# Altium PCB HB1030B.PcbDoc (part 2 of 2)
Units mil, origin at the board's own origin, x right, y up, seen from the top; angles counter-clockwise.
Board outline 1259.84 x 2086.61 mil, 2 copper layers (Top Layer, Bottom Layer); 36 components, 40 nets, 161 pads, 288 vias.
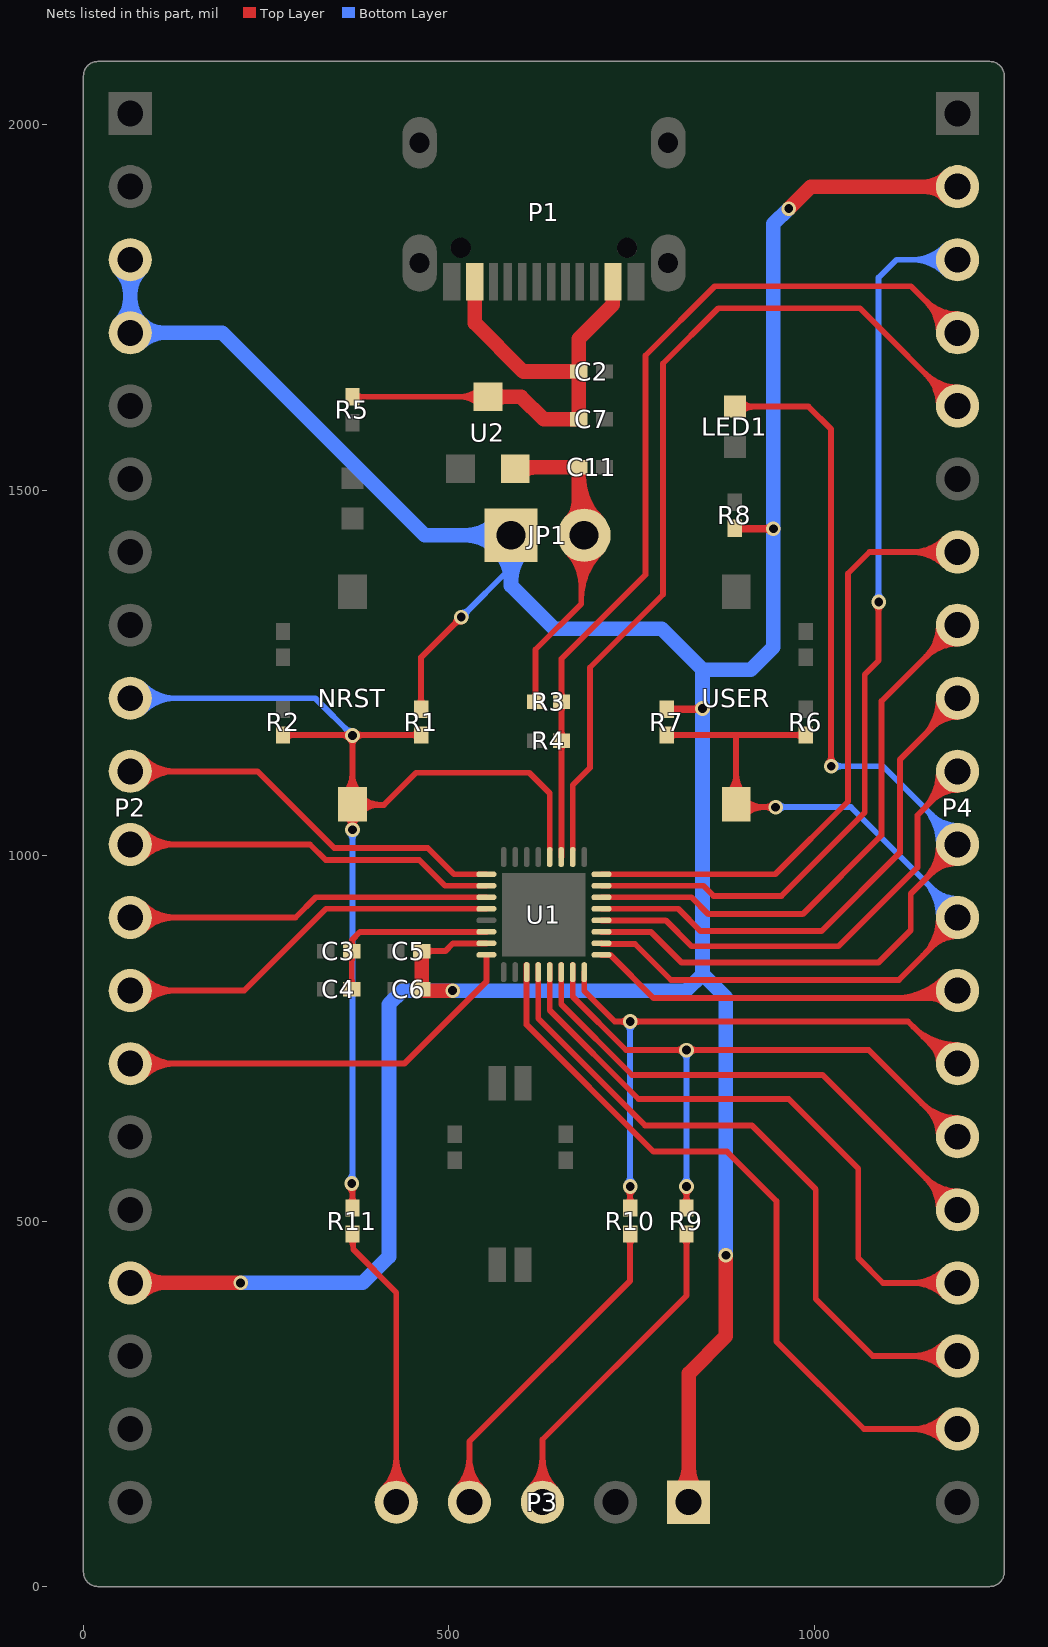
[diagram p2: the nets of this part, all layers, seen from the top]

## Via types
v1: diameter 20, hole 12, Top Layer to Bottom Layer, tented both sides, 284 vias
v2: diameter 25.98, hole 12.99, Top Layer to Bottom Layer, tented top, 4 vias

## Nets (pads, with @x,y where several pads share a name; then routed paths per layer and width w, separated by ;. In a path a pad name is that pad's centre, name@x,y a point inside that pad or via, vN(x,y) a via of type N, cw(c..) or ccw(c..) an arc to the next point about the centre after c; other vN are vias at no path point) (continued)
PA4: P2.10 U1.9 | length 713.9
  Top Layer w8: P2.10@59,1115.37 P2.10@64,1115.37 238,1115.37 343,1010.37 471,1010.37 506.88,974.49 U1.9@551.26,974.49 ; P2.10@76.39,1102.98 cw(c106.32,1073.06) 106.32,1115.37 cw(c106.32,1157.69) P2.10@76.39,1127.77 ; P2.10@82.05,1097.32 cw(c125.63,1053.75) 125.63,1115.37 cw(c125.63,1177) P2.10@82.05,1133.42
PA5: P2.11 U1.10 | length 679
  Top Layer w8: P2.11@59,1015.37 P2.11@64,1015.37 310,1015.37 331.4,993.97 459.4,993.97 494.63,958.74 U1.10@551.26,958.74 ; P2.11@76.39,1002.98 cw(c106.32,973.06) 106.32,1015.37 cw(c106.32,1057.69) P2.11@76.39,1027.77 ; P2.11@82.05,997.32 cw(c125.63,953.75) 125.63,1015.37 cw(c125.63,1077) P2.11@82.05,1033.42
PA6: P2.12 U1.11 | length 662.9
  Top Layer w8: P2.12@64,915.37 290,915.37 317.62,943 U1.11@551.26,943 ; P2.12@68.62,905.75 P2.12@69.24,906.37 ; P2.12@76.39,902.98 cw(c106.32,873.06) 106.32,915.37 cw(c106.32,957.69) P2.12@76.39,927.77 ; P2.12@82.05,897.32 cw(c125.63,853.75) 125.63,915.37 cw(c125.63,977) P2.12@82.05,933.42
PA7: P2.13 U1.12 | length 676.9
  Top Layer w8: P2.13@76.39,802.98 cw(c106.32,773.06) 106.32,815.37 cw(c106.32,857.69) P2.13@76.39,827.77 ; P2.13@82.05,797.32 cw(c125.63,753.75) 125.63,815.37 cw(c125.63,877) P2.13@82.05,833.42 ; P2.13@84,815.37 220,815.37 331.87,927.25 U1.12@551.26,927.25
PA8: P2.14 U1.16 | length 738.7
  Top Layer w8: P2.14@59,715.37 439,715.37 551.26,827.63 U1.16@551.26,864.26 ; P2.14@76.39,702.98 cw(c106.32,673.06) 106.32,715.37 cw(c106.32,757.69) P2.14@76.39,727.77 ; P2.14@82.05,697.32 cw(c125.63,653.75) 125.63,715.37 cw(c125.63,777) P2.14@82.05,733.42
PA9: P4.19 U1.19 | length 1181.5
  Top Layer w8: U1.19@606.38,850.63 U1.19@606.38,840.63 606.38,768.62 780,595 880.37,595 948,527.37 948,335.37 1068,215.37 P4.19@1196,215.37 P4.19@1201,215.37 ; P4.19@1177.95,197.32 ccw(c1134.37,153.75) 1134.37,215.37 ccw(c1134.37,277) P4.19@1177.95,233.42 ; P4.19@1183.61,202.98 ccw(c1153.68,173.06) 1153.68,215.37 ccw(c1153.68,257.69) P4.19@1183.61,227.77
PA10: P4.18 U1.20 | length 1094.8
  Top Layer w8: U1.20@622.13,850.63 U1.20@622.13,840.63 622.13,777.03 768.16,631 914.37,631 1002,543.37 1002,393.37 1080,315.37 P4.18@1196,315.37 P4.18@1201,315.37 ; P4.18@1177.95,297.32 ccw(c1134.37,253.75) 1134.37,315.37 ccw(c1134.37,377) P4.18@1177.95,333.42 ; P4.18@1183.61,302.98 ccw(c1153.68,273.06) 1153.68,315.37 ccw(c1153.68,357.69) P4.18@1183.61,327.77
PA11: P4.17 U1.21 | length 1014.9
  Top Layer w8: U1.21@637.87,850.63 U1.21@637.87,840.63 637.87,788.5 759.37,667 965,667 1060,572 1060,449.37 1094,415.37 P4.17@1201,415.37 ; P4.17@1177.95,397.32 ccw(c1134.37,353.75) 1134.37,415.37 ccw(c1134.37,477) P4.17@1177.95,433.42 ; P4.17@1183.61,402.98 ccw(c1153.68,373.06) 1153.68,415.37 ccw(c1153.68,457.69) P4.17@1183.61,427.77
PA12: P4.16 U1.22 | length 886.8
  Top Layer w8: U1.22@653.62,829.95 U1.22@653.62,840.63 ; U1.22@653.62,850.63 U1.22@653.62,840.63 ; P4.16@1170.47,515.37 ccw(c1108.84,515.37) 1152.42,558.95 ccw(c1196,602.53) P4.16@1196,540.9 ; P4.16@1178.47,515.37 ccw(c1136.16,515.37) 1166.08,545.3 ccw(c1196,575.22) P4.16@1196,532.9 ; P4.16@1196,515.37 1011.37,700 750.37,700 653.62,796.75 U1.22@653.62,840.63
PA13: P4.15 R9.1 U1.23 | length 1311.2
  Top Layer w8: U1.23@669.37,835.42 U1.23@669.37,840.63 ; U1.23@669.37,850.63 U1.23@669.37,840.63 ; R9.1@825,517.81 v1(825,547.37) ; 1147.3,661.07 ccw(c1196,709.77) P4.15@1196,640.9 ; 1154.54,653.83 cw(c1116.09,615.37) P4.15@1170.47,615.37 ; 1160.96,647.42 ccw(c1196,682.46) P4.15@1196,632.9 ; 1168.2,640.17 cw(c1143.4,615.37) P4.15@1178.47,615.37 ; P4.15@1201,615.37 1193,615.37 1074.37,734 742.37,734 669.37,807 U1.23@669.37,840.63 ; 810.51,734 cw(c810.51,719.51) 820.76,729.76 ccw(c810.51,719.51) 810.51,734 ; 810.51,734 ccw(c810.51,748.49) 820.76,738.24 cw(c810.51,748.49) 810.51,734 ; 825,532.89 cw(c839.49,532.89) 829.24,543.13 ccw(c839.49,532.89) 825,532.89 ; 825,532.89 ccw(c810.51,532.89) 820.76,543.13 cw(c810.51,532.89) 825,532.89 ; 825,533.88 cw(c810.9,533.88) 820.87,523.91 ccw(c810.9,533.88) 825,533.88 ; 825,533.88 ccw(c839.1,533.88) 829.13,523.91 cw(c839.1,533.88) 825,533.88 ; 839.49,734 cw(c839.49,748.49) 829.24,738.24 ccw(c839.49,748.49) 839.49,734 ; 839.49,734 ccw(c839.49,719.51) 829.24,729.76 cw(c839.49,719.51) 839.49,734
  Bottom Layer w8: v1(825,547.37) v1(825,734) ; 825,561.86 cw(c810.51,561.86) 820.76,551.62 ccw(c810.51,561.86) 825,561.86 ; 825,561.86 ccw(c839.49,561.86) 829.24,551.62 cw(c839.49,561.86) 825,561.86 ; 825,719.51 cw(c839.49,719.51) 829.24,729.76 ccw(c839.49,719.51) 825,719.51 ; 825,719.51 ccw(c810.51,719.51) 820.76,729.76 cw(c810.51,719.51) 825,719.51
PA14: P4.14 R10.1 U1.24 | length 1298.8
  Top Layer w8: U1.24@685.12,840.63 685.12,814.88 727,773 1128,773 1185.63,715.37 P4.14@1201,715.37 ; R10.1@748,517.81 v1(748,547.37) ; 1134.71,766.29 ccw(c1196,827.58) P4.14@1196,740.9 ; 1148.37,752.63 ccw(c1196,800.26) P4.14@1196,732.9 ; 1159.76,741.24 cw(c1133.89,715.37) P4.14@1170.47,715.37 ; 1162.03,738.97 ccw(c1196,772.95) P4.14@1196,724.9 ; P4.14@1195,716.37 P4.14@1196,715.37 ; 733.51,773 cw(c733.51,758.51) 743.76,768.76 ccw(c733.51,758.51) 733.51,773 ; 733.51,773 ccw(c733.51,787.49) 743.76,777.24 cw(c733.51,787.49) 733.51,773 ; 748,532.89 cw(c762.49,532.89) 752.24,543.13 ccw(c762.49,532.89) 748,532.89 ; 748,532.89 ccw(c733.51,532.89) 743.76,543.13 cw(c733.51,532.89) 748,532.89 ; 748,533.88 cw(c733.9,533.88) 743.87,523.91 ccw(c733.9,533.88) 748,533.88 ; 748,533.88 ccw(c762.1,533.88) 752.13,523.91 cw(c762.1,533.88) 748,533.88 ; 762.49,773 cw(c762.49,787.49) 752.24,777.24 ccw(c762.49,787.49) 762.49,773 ; 762.49,773 ccw(c762.49,758.51) 752.24,768.76 cw(c762.49,758.51) 762.49,773
  Bottom Layer w8: v1(748,547.37) v1(748,773) ; 748,561.86 cw(c733.51,561.86) 743.76,551.62 ccw(c733.51,561.86) 748,561.86 ; 748,561.86 ccw(c762.49,561.86) 752.24,551.62 cw(c762.49,561.86) 748,561.86 ; 748,758.51 cw(c762.49,758.51) 752.24,768.76 ccw(c762.49,758.51) 748,758.51 ; 748,758.51 ccw(c733.51,758.51) 743.76,768.76 cw(c733.51,758.51) 748,758.51
PA15: P4.13 U1.25 | length 754.1
  Top Layer w8: U1.25@708.74,864.26 720.74,864.26 780,805 1185.63,805 P4.13@1196,815.37 ; 1109.33,805 ccw(c1109.33,902.05) P4.13@1177.95,833.42 ; 1128.64,805 ccw(c1128.64,882.73) P4.13@1183.61,827.77 ; 1147.95,805 ccw(c1147.95,863.42) P4.13@1189.26,822.11 ; 1159.42,805 cw(c1159.42,778.79) P4.13@1177.95,797.32 ; 1167.27,805 ccw(c1167.27,844.11) P4.13@1194.92,816.45 ; P4.13@1198.5,812.87 P4.13@1201,815.37
PB3: P4.12 R6.2 R7.1 U1.26 USER.2 | length 1885.5
  Top Layer w8: U1.26@708.74,880 709.49,879.26 754.74,879.26 804,830 1115.63,830 P4.12@1201,915.37 ; R7.1@798,1164.94 893,1164.94 ; USER.2@881.91,1085.06 ccw(c855.13,1111.84) 893,1111.84 ccw(c930.87,1111.84) USER.2@904.09,1085.06 ; USER.2@904.09,1055.01 cw(c931.53,1027.57) 931.53,1066.37 ; USER.2@904.09,1077.19 ccw(c930.2,1103.3) 930.2,1066.37 ; v1(947,1066.37) 896.66,1066.37 USER.2@893,1070.04 893,1164.94 ; R6.2@988,1164.94 893,1164.94 ; 1148.89,863.26 ccw(c1096.77,915.37) P4.12@1170.47,915.37 ; 1160.96,875.33 cw(c1196,840.29) P4.12@1196,889.85 ; 1162.54,876.92 ccw(c1124.09,915.37) P4.12@1178.47,915.37 ; 1174.61,888.99 cw(c1196,867.6) P4.12@1196,897.85 ; 1176.2,890.57 ccw(c1151.4,915.37) P4.12@1186.47,915.37 ; 812.1,1164.94 cw(c812.1,1179.05) 802.13,1169.07 ccw(c812.1,1179.05) 812.1,1164.94 ; 812.1,1164.94 ccw(c812.1,1150.84) 802.13,1160.81 cw(c812.1,1150.84) 812.1,1164.94 ; 932.51,1066.37 cw(c932.51,1051.89) 942.76,1062.13 ccw(c932.51,1051.89) 932.51,1066.37 ; 932.51,1066.37 ccw(c932.51,1080.86) 942.76,1070.62 cw(c932.51,1080.86) 932.51,1066.37 ; 973.9,1164.94 cw(c973.9,1150.84) 983.87,1160.81 ccw(c973.9,1150.84) 973.9,1164.94 ; 973.9,1164.94 ccw(c973.9,1179.05) 983.87,1169.07 cw(c973.9,1179.05) 973.9,1164.94
  Bottom Layer w8: v1(947,1066.37) 1050,1066.37 P4.12@1201,915.37 ; 1148.89,967.49 cw(c1096.77,915.37) P4.12@1170.47,915.37 ; 1160.96,955.42 ccw(c1196,990.46) P4.12@1196,940.9 ; 1162.54,953.83 cw(c1124.09,915.37) P4.12@1178.47,915.37 ; 1174.61,941.76 ccw(c1196,963.15) P4.12@1196,932.9 ; 1176.2,940.17 cw(c1151.4,915.37) P4.12@1186.47,915.37 ; 961.49,1066.37 cw(c961.49,1080.86) 951.24,1070.62 ccw(c961.49,1080.86) 961.49,1066.37 ; 961.49,1066.37 ccw(c961.49,1051.89) 951.24,1062.13 cw(c961.49,1051.89) 961.49,1066.37
PB4: LED1.2 P4.11 U1.27 | length 1959
  Top Layer w8: U1.27@708.74,895.75 776.25,895.75 818,854 1088,854 1132,898 1132,948 1196,1012 P4.11@1196,1015.37 ; LED1.2@891.35,1614.37 992,1614.37 1023,1583.37 v1(1023,1122.37) ; 1150.04,966.04 ccw(c1100.7,1015.37) P4.11@1170.47,1015.37 ; 1158.18,974.18 cw(c1196,936.36) P4.11@1196,989.85 ; 1163.69,979.69 ccw(c1128.01,1015.37) P4.11@1178.47,1015.37 ; 1171.84,987.84 cw(c1196,963.68) P4.11@1196,997.85 ; 917.9,1614.37 cw(c917.9,1640.93) 899.12,1622.15 ccw(c917.9,1640.93) 917.9,1614.37 ; 917.9,1614.37 ccw(c917.9,1587.82) 899.12,1606.6 cw(c917.9,1587.82) 917.9,1614.37 ; 1023,1136.86 cw(c1008.51,1136.86) 1018.76,1126.62 ccw(c1008.51,1136.86) 1023,1136.86 ; 1023,1136.86 ccw(c1037.49,1136.86) 1027.24,1126.62 cw(c1037.49,1136.86) 1023,1136.86
  Bottom Layer w8: v1(1023,1122.37) 1094,1122.37 P4.11@1201,1015.37 ; 1148.89,1067.49 cw(c1096.77,1015.37) P4.11@1170.47,1015.37 ; 1160.96,1055.42 ccw(c1196,1090.46) P4.11@1196,1040.9 ; 1162.54,1053.83 cw(c1124.09,1015.37) P4.11@1178.47,1015.37 ; 1174.61,1041.76 ccw(c1196,1063.15) P4.11@1196,1032.9 ; 1176.2,1040.17 cw(c1151.4,1015.37) P4.11@1186.47,1015.37 ; 1037.49,1122.37 cw(c1037.49,1136.86) 1027.24,1126.62 ccw(c1037.49,1136.86) 1037.49,1122.37 ; 1037.49,1122.37 ccw(c1037.49,1107.89) 1027.24,1118.13 cw(c1037.49,1107.89) 1037.49,1122.37
PB5: P4.10 U1.28 | length 838.7
  Top Layer w8: U1.28@708.74,911.5 796.5,911.5 832,876 1033,876 1141,984 1141,1055.37 P4.10@1201,1115.37 ; 1148.89,1063.26 ccw(c1096.77,1115.37) P4.10@1170.47,1115.37 ; 1160.96,1075.33 cw(c1196,1040.29) P4.10@1196,1089.85 ; 1162.54,1076.92 ccw(c1124.09,1115.37) P4.10@1178.47,1115.37 ; 1174.61,1088.99 cw(c1196,1067.6) P4.10@1196,1097.85 ; 1176.2,1090.57 ccw(c1151.4,1115.37) P4.10@1186.47,1115.37
PB6: P4.9 U1.29 | length 902.1
  Top Layer w8: U1.29@708.74,927.25 813.75,927.25 844,897 1010,897 1117,1004 1117,1131.37 P4.9@1201,1215.37 ; 1148.89,1163.26 ccw(c1096.77,1215.37) P4.9@1170.47,1215.37 ; 1160.96,1175.33 cw(c1196,1140.29) P4.9@1196,1189.85 ; 1162.54,1176.92 ccw(c1124.09,1215.37) P4.9@1178.47,1215.37 ; 1174.61,1188.99 cw(c1196,1167.6) P4.9@1196,1197.85 ; 1176.2,1190.57 ccw(c1151.4,1215.37) P4.9@1186.47,1215.37
PB7: P4.8 U1.30 | length 931.2
  Top Layer w8: U1.30@708.74,943 832,943 855,920 984,920 1092,1028 1092,1211.37 P4.8@1196,1315.37 ; P4.8@1170.47,1315.37 cw(c1108.84,1315.37) 1152.42,1271.8 cw(c1196,1228.22) P4.8@1196,1289.85 ; P4.8@1178.47,1315.37 cw(c1136.16,1315.37) 1166.08,1285.45 cw(c1196,1255.53) P4.8@1196,1297.85
PB8: P4.7 U1.32 | length 1015.9
  Top Layer w8: U1.32@708.74,974.49 946.49,974.49 1046,1074 1046,1386 1075.37,1415.37 P4.7@1196,1415.37 ; P4.7@1177.95,1397.32 ccw(c1134.37,1353.75) 1134.37,1415.37 ccw(c1134.37,1477) P4.7@1177.95,1433.42 ; P4.7@1183.61,1402.98 ccw(c1153.68,1373.06) 1153.68,1415.37 ccw(c1153.68,1457.69) P4.7@1183.61,1427.77
PF1: P4.5 U1.2 | length 1369.4
  Top Layer w8: U1.2@669.37,1008.11 669.37,1096.74 693,1120.37 693,1257.37 793,1357.37 793,1673.37 868.63,1749 1062.37,1749 P4.5@1196,1615.37 ; P4.5@1170.47,1615.37 ccw(c1108.84,1615.37) 1152.42,1658.95 ccw(c1196,1702.53) P4.5@1196,1640.9 ; P4.5@1178.47,1615.37 ccw(c1136.16,1615.37) 1166.08,1645.3 ccw(c1196,1675.22) P4.5@1196,1632.9
PF2: P4.4 R3.1 R4.1 U1.3 | length 1566.6
  Top Layer w8: U1.3@654,998.49 R4.1@654,1157.37 R3.1@654,1210.37 654,1269.37 769,1384.37 769,1684.37 863.63,1779 1132.37,1779 P4.4@1196,1715.37 ; P4.4@1170.47,1715.37 ccw(c1108.84,1715.37) 1152.42,1758.95 ccw(c1196,1802.53) P4.4@1196,1740.9 ; P4.4@1178.47,1715.37 ccw(c1136.16,1715.37) 1166.08,1745.3 ccw(c1196,1775.22) P4.4@1196,1732.9 ; 654,1143.27 cw(c668.1,1143.27) 658.13,1153.24 ccw(c668.1,1143.27) 654,1143.27 ; 654,1143.27 ccw(c639.9,1143.27) 649.87,1153.24 cw(c639.9,1143.27) 654,1143.27 ; 654,1171.48 cw(c639.9,1171.48) 649.87,1161.51 ccw(c639.9,1171.48) 654,1171.48 ; 654,1171.48 ccw(c668.1,1171.48) 658.13,1161.51 cw(c668.1,1171.48) 654,1171.48 ; 654,1196.27 cw(c668.1,1196.27) 658.13,1206.24 ccw(c668.1,1196.27) 654,1196.27 ; 654,1196.27 ccw(c639.9,1196.27) 649.87,1206.24 cw(c639.9,1196.27) 654,1196.27 ; 654,1224.48 cw(c639.9,1224.48) 649.87,1214.51 ccw(c639.9,1224.48) 654,1224.48 ; 654,1224.48 ccw(c668.1,1224.48) 658.13,1214.51 cw(c668.1,1224.48) 654,1224.48
PF3: NRST.2 P2.9 R1.2 R2.1 R11.1 U1.4 | length 2422.3
  Top Layer w8: R2.1@273,1164.94 v1@367.43,1164.94 ; NRST.2@356.91,1085.06 ccw(c330.13,1111.84) 368,1111.84 ccw(c405.87,1111.84) NRST.2@379.09,1085.06 ; v1(367,551.37) 368,550.37 R11.1@368,517.81 ; v1(368,1164.37) NRST.2@368,1070.04 ; v1@368.57,1164.94 R1.2@462,1164.94 ; NRST.2@373.43,1075.47 ccw(c388.15,1090.19) 388.15,1069.37 ; NRST.2@379.09,1058.94 cw(c404.27,1033.77) 404.27,1069.37 ; NRST.2@379.09,1081.13 ccw(c407.46,1109.5) 407.46,1069.37 ; U1.4@637.87,1008.11 637.87,1085.5 610,1113.37 455,1113.37 411,1069.37 368.66,1069.37 NRST.2@368,1070.04 ; 287.1,1164.94 cw(c287.1,1179.05) 277.13,1169.07 ccw(c287.1,1179.05) 287.1,1164.94 ; 287.1,1164.94 ccw(c287.1,1150.84) 277.13,1160.81 cw(c287.1,1150.84) 287.1,1164.94 ; v1@363.76,1160.13 ccw(c352.15,1148.52) 352.15,1164.94 cw(c352.15,1148.52) v1@363.76,1160.13 ; v1@363.76,1160.13 cw(c353.51,1149.89) 368,1149.89 ; v1@363.76,1160.13 cw(c353.51,1149.89) 368,1149.89 ; 368,533.88 cw(c353.9,533.88) 363.87,523.91 ccw(c353.9,533.88) 368,533.88 ; 368,533.88 ccw(c382.1,533.88) 372.13,523.91 cw(c382.1,533.88) 368,533.88 ; v1(368,1035.37) cw(c390.25,1035.38) 377.2,1053.39 ccw(c390.25,1035.38) v1(368,1035.37) ; v1(368,1035.37) ccw(c345.75,1035.38) 358.8,1053.39 cw(c345.75,1035.38) v1(368,1035.37) ; v1(368,1035.37) NRST.2@368,1070.04 ; NRST.2@368,1049.86 cw(c353.51,1049.86) 363.76,1039.62 ccw(c353.51,1049.86) NRST.2@368,1049.86 ; NRST.2@368,1049.86 ccw(c382.49,1049.86) 372.24,1039.62 cw(c382.49,1049.86) NRST.2@368,1049.86 ; 368,1149.89 cw(c382.49,1149.89) v1@372.24,1160.13 ; 368,1149.89 cw(c382.49,1149.89) v1@372.24,1160.13 ; v1@372.24,1160.13 cw(c383.85,1148.52) 383.85,1164.94 ccw(c383.85,1148.52) v1@372.24,1160.13 ; 447.9,1164.94 cw(c447.9,1150.84) 457.87,1160.81 ccw(c447.9,1150.84) 447.9,1164.94 ; 447.9,1164.94 ccw(c447.9,1179.05) 457.87,1169.07 cw(c447.9,1179.05) 447.9,1164.94 ; 354.88,1164.94 ccw(c354.88,1177.49) 363.76,1168.62 cw(c354.88,1177.49) 354.88,1164.94 ; v1@362.76,547.13 cw(c350.1,534.47) 368,534.47 ccw(c350.1,534.47) v1@362.76,547.13 ; 368,539.3 cw(c379.07,539.3) 371.24,547.13 ccw(c379.07,539.3) 368,539.3 ; v1@372.24,1168.62 ccw(c381.12,1177.49) 381.12,1164.94 cw(c381.12,1177.49) v1@372.24,1168.62
  Bottom Layer w8: P2.9@59,1215.37 P2.9@64,1215.37 317,1215.37 v1(368,1164.37) ; P2.9@76.39,1202.98 cw(c106.32,1173.06) 106.32,1215.37 cw(c106.32,1257.69) P2.9@76.39,1227.77 ; P2.9@82.05,1197.32 cw(c125.63,1153.75) 125.63,1215.37 cw(c125.63,1277) P2.9@82.05,1233.42 ; v1(367,551.37) 368,552.37 v1(368,1035.37) ; 357.76,1174.62 cw(c347.51,1164.37) 362,1164.37 ccw(c347.51,1164.37) 357.76,1174.62 ; 357.76,1174.62 ccw(c368,1184.86) 368,1170.37 cw(c368,1184.86) 357.76,1174.62 ; 368,1020.89 cw(c382.49,1020.89) 372.24,1031.13 ccw(c382.49,1020.89) 368,1020.89 ; 368,1020.89 ccw(c353.51,1020.89) 363.76,1031.13 cw(c353.51,1020.89) 368,1020.89 ; v1@362.76,555.62 ccw(c350.1,568.27) 368,568.27 cw(c350.1,568.27) v1@362.76,555.62 ; 368,563.45 ccw(c379.07,563.45) 371.24,555.62 cw(c379.07,563.45) 368,563.45
PF4: P4.3 U1.31 | length 1525.4
  Top Layer w8: U1.31@708.74,958.74 848.26,958.74 862,945 955,945 1069,1059 1069,1248 1088,1267 v1(1088,1347) ; 1088,1332.51 cw(c1102.49,1332.51) 1092.24,1342.76 ccw(c1102.49,1332.51) 1088,1332.51 ; 1088,1332.51 ccw(c1073.51,1332.51) 1083.76,1342.76 cw(c1073.51,1332.51) 1088,1332.51
  Bottom Layer w8: v1(1088,1347) 1088,1791 1112.37,1815.37 P4.3@1196,1815.37 ; P4.3@1177.95,1797.32 ccw(c1134.37,1753.75) 1134.37,1815.37 ccw(c1134.37,1877) P4.3@1177.95,1833.42 ; P4.3@1183.61,1802.98 ccw(c1153.68,1773.06) 1153.68,1815.37 ccw(c1153.68,1857.69) P4.3@1183.61,1827.77 ; 1088,1361.49 cw(c1073.51,1361.49) 1083.76,1351.24 ccw(c1073.51,1361.49) 1088,1361.49 ; 1088,1361.49 ccw(c1102.49,1361.49) 1092.24,1351.24 cw(c1102.49,1361.49) 1088,1361.49
RESET: P3.5 R11.2 | length 599
  Top Layer w8: R11.2@369,482.37 369,461.37 428,402.37 P3.5@428,115.37 ; P3.5@409.95,133.42 ccw(c366.37,177) 428,177 ccw(c489.63,177) P3.5@446.05,133.42 ; P3.5@415.61,127.77 ccw(c385.68,157.69) 428,157.69 ccw(c470.32,157.69) P3.5@440.39,127.77 ; R11.2@363.87,476.27 cw(c351.48,463.89) 369,463.89 ccw(c351.48,463.89) R11.2@363.87,476.27 ; 369,468.71 cw(c379.69,468.71) 372.13,476.27 ccw(c379.69,468.71) 369,468.71
SWCLK: P3.4 R10.2 | length 677.7
  Top Layer w8: P3.4@509.95,133.42 ccw(c466.37,177) 528,177 ccw(c589.63,177) P3.4@546.05,133.42 ; P3.4@515.61,127.77 ccw(c485.68,157.69) 528,157.69 ccw(c570.32,157.69) P3.4@540.39,127.77 ; P3.4@528,115.37 528,198.37 748,418.37 748,470.37 ; 748,466.3 cw(c762.1,466.3) 752.13,476.27 ccw(c762.1,466.3) 748,466.3 ; 748,466.3 ccw(c733.9,466.3) 743.87,476.27 cw(c733.9,466.3) 748,466.3 ; 748,470.37 cw(c753.69,470.37) 750.88,475.32 ccw(c753.69,470.37) 748,470.37 ; 748,470.37 ccw(c742.31,470.37) 745.12,475.32 cw(c742.31,470.37) 748,470.37
SWDIO: P3.3 R9.2 | length 668.2
  Top Layer w8: P3.3@609.95,133.42 ccw(c566.37,177) 628,177 ccw(c689.63,177) P3.3@646.05,133.42 ; P3.3@615.61,127.77 ccw(c585.68,157.69) 628,157.69 ccw(c670.32,157.69) P3.3@640.39,127.77 ; P3.3@628,115.37 628,201 825,398 825,470.37 ; 825,466.3 cw(c839.1,466.3) 829.13,476.27 ccw(c839.1,466.3) 825,466.3 ; 825,466.3 ccw(c810.9,466.3) 820.87,476.27 cw(c810.9,466.3) 825,466.3 ; 825,470.37 cw(c830.69,470.37) 827.88,475.32 ccw(c830.69,470.37) 825,470.37 ; 825,470.37 ccw(c819.31,470.37) 822.12,475.32 cw(c819.31,470.37) 825,470.37
VBUS_5V: C2.2 C7.2 P1.A4 P1.A9 P1.B4 P1.B9 R5.2 U2.3 | length 933.3
  Top Layer w8: R5.2@368,1627.81 U2.3@553.4,1627.8 ; U2.3@542.31,1616.71 ccw(c515.53,1589.93) 515.53,1627.8 ccw(c515.53,1665.67) U2.3@542.31,1638.89 ; 382.12,1627.8 cw(c382.12,1641.93) 372.13,1631.94 ccw(c382.12,1641.93) 382.12,1627.8 ; 382.09,1627.8 ccw(c382.09,1613.72) 372.13,1623.68 cw(c382.09,1613.72) 382.09,1627.8
  Top Layer w20: P1.B4@535.52,1785.23 535.52,1728.85 602,1662.37 C2.2@677.57,1662.37 ; U2.3@553.4,1627.8 598.57,1627.8 629.5,1596.87 C7.2@677.57,1596.87 C2.2@677.57,1662.37 ; P1.B9@724.31,1785.23 724.31,1753.69 677.57,1706.94 C2.2@677.57,1662.37 ; 576.78,1627.8 cw(c576.78,1651.18) 560.25,1634.65 ccw(c576.78,1651.18) 576.78,1627.8 ; 576.78,1627.8 ccw(c576.78,1604.42) 560.25,1620.95 cw(c576.78,1604.42) 576.78,1627.8
VCORE: C3.1 C4.1 U1.14 | length 389.3
  Top Layer w8: C4.1@367,816.97 367,884.37 378.38,895.75 U1.14@551.26,895.75 ; 367,831.08 cw(c352.9,831.08) 362.87,821.11 ccw(c352.9,831.08) 367,831.08 ; 367,831.08 ccw(c381.1,831.08) 371.13,821.11 cw(c381.1,831.08) 367,831.08 ; 367,855.27 cw(c381.1,855.27) 371.13,865.24 ccw(c381.1,855.27) 367,855.27 ; 367,855.27 ccw(c352.9,855.27) 362.87,865.24 cw(c352.9,855.27) 367,855.27 ; 367,883.48 cw(c352.9,883.48) 362.87,873.51 ccw(c352.9,883.48) 367,883.48 ; 367,883.48 ccw(c381.1,883.48) 371.13,873.51 cw(c381.1,883.48) 367,883.48
VDD: C5.2 C6.2 JP1.1 P2.3 P2.4 P2.17 P3.1 P4.2 R1.1 R7.2 R8.2 U1.15 | length 6160.9
  Top Layer w8: R1.1@462,1200.37 462,1271.37 v1(517,1326.37) ; C5.2@463,869.37 495,869.37 505.63,880 U1.15@551.26,880 ; 462,1216.45 cw(c447.9,1216.45) 457.87,1206.47 ccw(c447.9,1216.45) 462,1216.45 ; 462,1216.45 ccw(c476.1,1216.45) 466.13,1206.47 cw(c476.1,1216.45) 462,1216.45 ; 479.07,869.37 cw(c479.07,883.48) 469.1,873.51 ccw(c479.07,883.48) 479.07,869.37 ; 479.07,869.37 ccw(c479.07,855.27) 469.1,865.24 cw(c479.07,855.27) 479.07,869.37 ; 506.76,1316.13 cw(c517,1305.89) 517,1320.37 ccw(c517,1305.89) 506.76,1316.13 ; 506.76,1316.13 ccw(c496.51,1326.37) 511,1326.37 cw(c496.51,1326.37) 506.76,1316.13
  Top Layer w10: C6.2@462.43,815.37 C6.2@463,815.37 ; R7.2@798,1200.37 846,1200.37 v1(847,1201.37) ; P3.1@828,98.37 P3.1@828,103.37 ; R8.2@891.35,1447.94 891.91,1447.37 v1@943,1447.37 ; 809.69,1200.37 cw(c809.69,1212.06) 801.42,1203.8 ccw(c809.69,1212.06) 809.69,1200.37 ; 809.69,1200.37 ccw(c809.69,1188.68) 801.42,1196.95 cw(c809.69,1188.68) 809.69,1200.37 ; 931.93,1447.37 cw(c931.93,1435.3) 940.46,1443.84 ccw(c931.93,1435.3) 931.93,1447.37 ; 931.93,1447.37 ccw(c931.93,1459.45) 940.46,1450.91 cw(c931.93,1459.45) 931.93,1447.37 ; 832.51,1200.37 ccw(c832.51,1215.86) 843.46,1204.91 cw(c832.51,1215.86) 832.51,1200.37 ; R8.2@894.77,1444.52 cw(c901.67,1437.62) 901.67,1447.37 ccw(c901.67,1437.62) R8.2@894.77,1444.52 ; R8.2@894.77,1451.37 ccw(c904.41,1461) 904.41,1447.37 cw(c904.41,1461) R8.2@894.77,1451.37
  Top Layer w20: P2.17@64,415.37 v1(215,415.37) ; P2.17@77.81,401.57 cw(c111.14,368.23) 111.14,415.37 cw(c111.14,462.52) P2.17@77.81,429.18 ; C6.2@463,815.37 v1(505,815.37) ; C6.2@463,816.97 C5.2@463,869.37 ; P3.1@814.19,129.18 ccw(c780.86,162.52) 828,162.52 ccw(c875.14,162.52) P3.1@841.81,129.18 ; P3.1@828,115.37 828,291.37 879,342.37 v1(879,453.37) ; v1(965,1885.37) 995,1915.37 P4.2@1196,1915.37 ; P4.2@1182.19,1901.57 ccw(c1148.86,1868.23) 1148.86,1915.37 ccw(c1148.86,1962.52) P4.2@1182.19,1929.18
  Bottom Layer w8: v1(517,1326.37) 585,1394.37 ; JP1.1@585,1438.37 JP1.1@609,1438.37 ; 527.24,1336.62 cw(c517,1346.86) 517,1332.37 ccw(c517,1346.86) 527.24,1336.62 ; 527.24,1336.62 ccw(c537.49,1326.37) 523,1326.37 cw(c537.49,1326.37) 527.24,1336.62
  Bottom Layer w10: P3.1@828,98.37 P3.1@848,118.37
  Bottom Layer w20: P2.4@50.19,1729.18 ccw(c16.86,1762.52) 64,1762.52 ccw(c111.14,1762.52) 77.81,1729.18 ccw(c111.14,1762.52) 111.14,1715.37 ccw(c111.14,1668.23) P2.4@77.81,1701.57 ; P2.3@50.19,1801.57 cw(c16.86,1768.23) 64,1768.23 cw(c111.14,1768.23) P2.3@77.81,1801.57 ; P2.3@64,1815.37 P2.4@64,1715.37 190,1715.37 467,1438.37 JP1.1@585,1438.37 585,1394.37 ; v1(215,415.37) 382,415.37 418,451.37 418,796.37 437,815.37 v1(505,815.37) 824.37,815.37 847,838 ; JP1.1@566.32,1457.05 cw(c521.22,1502.15) 521.22,1438.37 cw(c521.22,1374.6) 566.32,1419.69 cw(c521.22,1374.6) 585,1374.6 cw(c648.78,1374.6) JP1.1@603.68,1419.69 ; 845,1256.37 791,1310.37 644,1310.37 585,1369.37 585,1394.37 ; v1(879,453.37) 879,806 847,838 ; v1(965,1885.37) 944,1864.37 v1(944,1447.37) 944,1285.37 913,1254.37 847,1254.37 v1(847,1201.37) 847,838 ; JP1.1@572.58,1415.06 cw(c561.57,1394.38) 585,1394.38 ; JP1.1@572.58,1415.06 cw(c561.57,1394.38) 585,1394.38 ; JP1.1@572.58,1415.06 cw(c561.57,1394.38) 585,1394.38 ; JP1.1@572.58,1415.06 cw(c561.57,1394.38) 585,1394.38 ; 585,1394.38 cw(c608.43,1394.38) JP1.1@597.42,1415.06 ; 585,1394.38 cw(c608.43,1394.38) JP1.1@597.42,1415.06 ; 585,1394.38 cw(c608.43,1394.38) JP1.1@597.42,1415.06 ; 585,1394.38 cw(c608.43,1394.38) JP1.1@597.42,1415.06
VLDO: C11.2 JP1.2 R3.2 U2.2 | length 883.5
  Top Layer w8: R3.2@618.57,1210.37 618.57,1281.94 681,1344.37 JP1.2@681,1438.37 ; JP1.2@662.08,1415.45 cw(c616.39,1369.77) 681,1369.77 cw(c753.61,1369.77) JP1.2@702.27,1421.11 ; JP1.2@667.73,1421.11 cw(c635.71,1389.08) 681,1389.08 cw(c734.29,1389.08) JP1.2@696.61,1426.77 ; 681,1350.45 cw(c772.92,1350.45) JP1.2@707.92,1415.45 ; 618.57,1224.48 cw(c604.46,1224.48) 614.44,1214.51 ccw(c604.46,1224.48) 618.57,1224.48 ; 618.57,1224.48 ccw(c632.67,1224.48) 622.7,1214.51 cw(c632.67,1224.48) 618.57,1224.48
  Top Layer w20: U2.2@592.71,1531.28 C11.2@677.57,1531.28 677.57,1445.81 JP1.2@685,1438.37 ; JP1.2@666.32,1457.05 ccw(c639.17,1484.21) 677.57,1484.21 ; 677.57,1520.1 ccw(c766.72,1520.1) JP1.2@703.68,1457.05 ; U2.2@597.65,1522.53 cw(c618.78,1501.39) 618.78,1531.28 ccw(c618.78,1501.39) U2.2@597.65,1522.53
pads on no net: P1. P1.A5 P1.A6 P1.A7 P1.A8 P1.B5 P1.B6 P1.B7 P1.B8

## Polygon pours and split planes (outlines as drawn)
GND on Top Layer "Top Layer-No Net" (solid, pour order 1000): -2.24,2090.59 1258.76,2090.59 1258.76,-0.61 -0.24,-0.61 -0.24,2088.55 -2.24,2090.59
GND on Bottom Layer "Top Layer-No Net" (solid, pour order 1001): -0.63,2087.13 1259.37,2087.13 1259.37,1.05 1258.37,0.03 -0.63,0.03 -0.63,2087.13

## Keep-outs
Keep-Out Layer:
  the board outline again, w8

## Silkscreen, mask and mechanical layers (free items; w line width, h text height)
Top Overlay:
  lines w8: 109,2065.37 225,2065.37 ; 113,65.37 229,65.37 229,2065.37 ; 114,167.37 229,167.37 ; 114,267.26 229,267.26 ; 114,367.15 229,367.15 ; 114,467.04 229,467.04 ; 114,566.93 229,566.93 ; 114,666.82 229,666.82 ; 114,766.71 229,766.71 ; 114,866.6 229,866.6 ; 114,966.48 229,966.48 ; 114,1066.37 229,1066.37 ; 114,1166.26 229,1166.26 ; 114,1266.15 229,1266.15 ; 114,1366.04 229,1366.04 ; 114,1465.93 229,1465.93 ; 114,1565.82 229,1565.82 ; 114,1665.71 229,1665.71 ; 114,1765.59 229,1765.59 ; 114,1865.48 229,1865.48 ; 114,1965.37 229,1965.37 ; 1031,167.37 1146,167.37 ; 1031,267.26 1146,267.26 ; 1031,367.15 1146,367.15 ; 1031,467.04 1146,467.04 ; 1031,566.93 1146,566.93 ; 1031,666.82 1146,666.82 ; 1031,766.71 1146,766.71 ; 1031,866.59 1146,866.59 ; 1031,966.48 1146,966.48 ; 1031,1066.37 1146,1066.37 ; 1031,1166.26 1146,1166.26 ; 1031,1266.15 1146,1266.15 ; 1031,1366.04 1146,1366.04 ; 1031,1465.93 1146,1465.93 ; 1031,1565.81 1146,1565.81 ; 1031,1665.7 1146,1665.7 ; 1031,1765.59 1146,1765.59 ; 1031,1865.48 1146,1865.48 ; 1031,1965.37 1146,1965.37 ; 1031,2065.37 1031,65.37 1151,65.37 ; 1035,2065.37 1151,2065.37
  text "GND" at 131.57,1999.95 h30
  text "GND" at 1050,1999.94 h30
  text "GND" at 131.57,1900.02 h30
  text "VDD" at 1050,1900.02 h30
  text "VDD" at 131.57,1800.1 h30
  text "PF4" at 1050,1800.09 h30
  text "LITE-32" at 980,1743.37 h45 r90
  text "HB1030B" at 903,1737.37 h45 r90
  text "VDD" at 131.57,1700.17 h30
  text "PF2" at 1050,1700.09 h30
  text "PA0" at 131.57,1600.25 h30
  text "PF1" at 1050,1600.24 h30
  text "PA1" at 131.57,1500.32 h30
  text "GND" at 1050,1500.32 h30
  text "PA2" at 131.57,1400.4 h30
  text "PB8" at 1050,1400.4 h30
  text "PwrTest" at 560,1337 h30
  text "PA3" at 131.57,1300.47 h30
  text "PB7" at 1050,1300.47 h30
  text "PF3" at 131.57,1200.55 h30
  text "PB6" at 1050,1200.55 h30
  text "PA4" at 131.57,1100.62 h30
  text "PB5" at 1050,1100.62 h30
  text "PA5" at 131.57,1000.7 h30
  text "PB4" at 1050,1000.7 h30
  text "PA6" at 131.57,900.77 h30
  text "PB3" at 1050,900.77 h30
  text "PA7" at 131.57,800.85 h30
  text "PA15" at 1040,800.85 h30
  text "PA8" at 131.57,700.92 h30
  text "PA14" at 1040,701.37 h30
  text "GND" at 131.57,601 h30
  text "PA13" at 1040,601 h30
  text "GND" at 131.57,501.07 h30
  text "PA12" at 1040,501.07 h30
  text "VDD" at 131.57,401.15 h30
  text "PA11" at 1040,401.15 h30
  text "GND" at 131.57,301.22 h30
  text "PA10" at 1040,301.22 h30
  text "GND" at 131.57,201.3 h30
  text "PA9" at 1050,201.3 h30
  text "RESET" at 442,181.37 h30 r90
  text "SWCLK" at 542.75,181.37 h30 r90
  text "SWDIO" at 643.5,181.37 h30 r90
  text "GND" at 744.25,181.37 h30 r90
  text "VDD" at 845,181.37 h30 r90
  text "GND" at 131.57,101.37 h30
  text "GND" at 1050,101.37 h30
Mechanical 1:
  the board outline again, w8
